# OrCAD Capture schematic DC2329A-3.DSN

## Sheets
1 PAGE1: size Custom; title: 17V, 3.5A DUAL SYNCHRONOUS STEP-DOWN; rev: 3; company: TM; note: REGULATOR WITH ULTRA-LOW QUIESCENT CURRENT
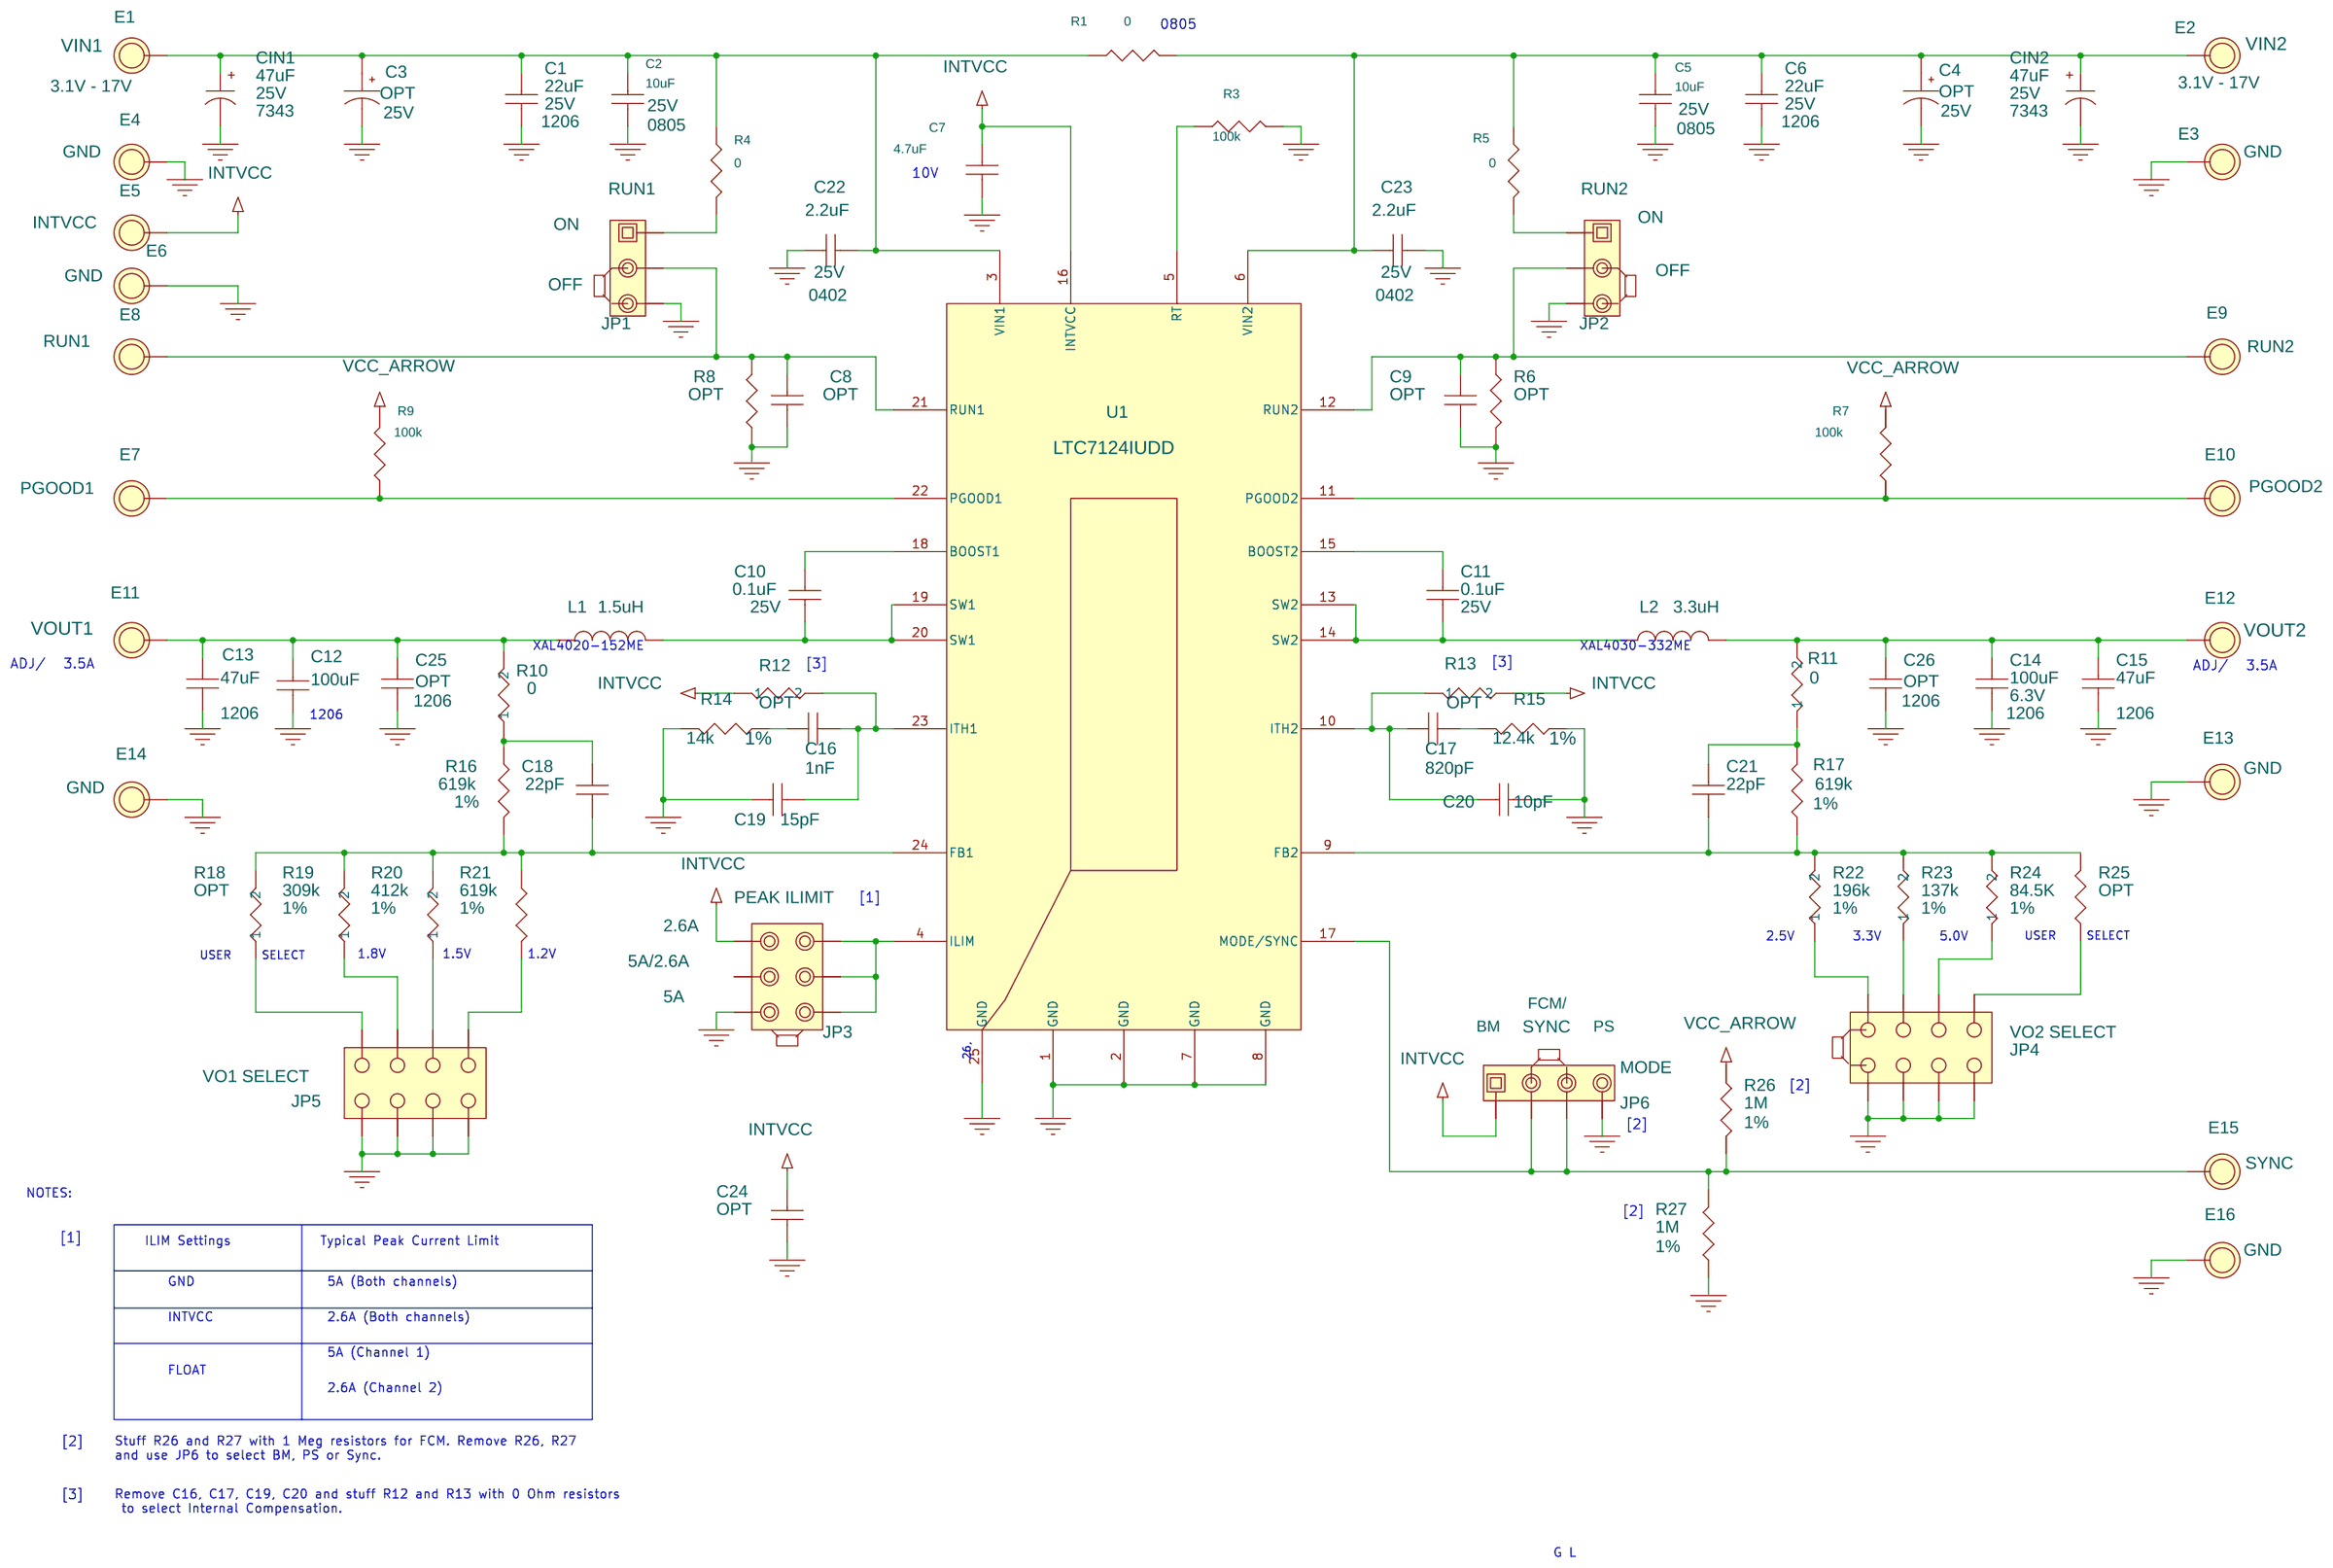
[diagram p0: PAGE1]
2 PAGE2: size A
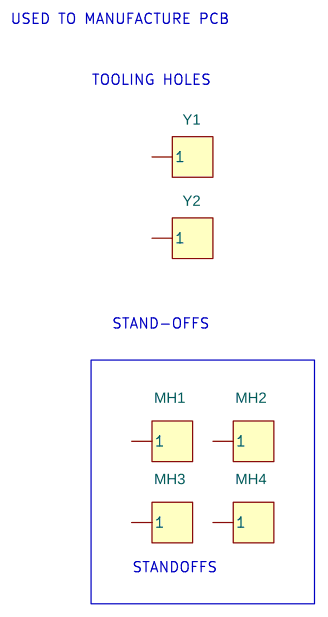
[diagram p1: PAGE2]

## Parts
sheet PAGE1
C1  22uF  [1206]
C2  10uF  [0805]
C3  OPT  [CAP\SANYO\SVPA_E7]
C4  OPT  [CAP\SANYO\SVPA_E7]
C5  10uF  [0805]
C6  22uF  [1206]
C7  4.7uF  [0603]
C8  OPT  [0603]
C9  OPT  [0603]
C10  0.1uF  [0603]
C11  0.1uF  [0603]
C12  100uF  [1206]
C13  47uF  [1206]
C14  100uF  [1206]
C15  47uF  [1206]
C16  1nF  [0603]
C17  820pF  [0603]
C18  22pF  [0603]
C19  15pF  [0603]
C20  10pF  [0603]
C21  22pF  [0603]
C22  2.2uF  [0402]
C23  2.2uF  [0402]
C24  OPT  [0603]
C25  OPT  [1206]
C26  OPT  [1206]
CIN1  47uF  [7343]
CIN2  47uF  [7343]
E1  3.1V - 17V  [TP\MMX\2501-2]
E2  3.1V - 17V  [TP\MMX\2501-2]
E3  2.7V - 17V  [TP\MMX\2501-2]
E4  2.7V - 17V  [TP\MMX\2501-2]
E5  3.6V  [TP\MMX\2501-2]
E6  2.7V - 17V  [TP\MMX\2501-2]
E7  3A  [TP\MMX\2501-2]
E8  2.7V - 17V  [TP\MMX\2501-2]
E9  2.7V - 17V  [TP\MMX\2501-2]
E10  3A  [TP\MMX\2501-2]
E11  ADJ  [TP\MMX\2501-2]
E12  ADJ  [TP\MMX\2501-2]
E13  2.7V - 17V  [TP\MMX\2501-2]
E14  2.7V - 17V  [TP\MMX\2501-2]
E15  3A  [TP\MMX\2501-2]
E16  2.7V - 17V  [TP\MMX\2501-2]
JP1  3 Pins 2mm Ctrs.  [SIP\3P\2MM]
JP2  3 Pins 2mm Ctrs.  [SIP\3P\2MM]
JP3  2 Pins 2mm Ctrs.  [HDR\3X2\2MM]
JP4  VO2 SELECT  [HDR2X4_2MM]
JP5  VO1 SELECT  [HDR2X4_2MM]
JP6  3 Pins 2mm Ctrs.  [HDR_1X4_2MM]
L1  1.5uH  [IND\CLCRFT\XAL4020]
L2  3.3uH  [IND\CLCRFT\XAL4030]
R1  0  [0805]
R3  100k  [0603]
R4  0  [0603]
R5  0  [0603]
R6  OPT  [0603]
R7  100k  [0603]
R8  OPT  [0603]
R9  100k  [0603]
R10  0  [0603]
R11  0  [0603]
R12  OPT  [0603]
R13  OPT  [0603]
R14  14k  [0603]
R15  12.4k  [0603]
R16  619k  [0603]
R17  619k  [0603]
R18  OPT  [0603]
R19  309k  [0603]
R20  412k  [0603]
R21  619k  [0603]
R22  196k  [0603]
R23  137k  [0603]
R24  84.5K  [0603]
R25  OPT  [0603]
R26  1M  [0603]
R27  1M  [0603]
U1  LTC7124IUDD  [LT_UDD24_3X5]
XJP1  2mm Ctrs.
XJP2  2mm Ctrs.
XJP3  2mm Ctrs.
XJP4  2mm Ctrs.
XJP5  2mm Ctrs.
XJP6  2mm Ctrs.
sheet PAGE2
MH1  CON1  [KEYSTONE_8831]
MH2  CON1  [KEYSTONE_8831]
MH3  CON1  [KEYSTONE_8831]
MH4  CON1  [KEYSTONE_8831]
Y1  CON1  [TOOL\ALGNHL\70]
Y2  CON1  [TOOL\ALGNHL\70]

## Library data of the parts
C1 C6 = CAP_NP: CAP, 1206 22uF10% 25V X5R; Part Number: AVX 12063D226KAT2A; Tolerance: X5R; Voltage: 25V
C2 C5 = CAP: CAP, 0805 10uF 10% 25V ,X5R; CLASS: DISCRETE; Dielectric Type: X5R; FPLIST: CC0805N,CC0805L,CC0805M; Manufacturer: MURATA; Manufacturer PN: GRM219R61E106KA12D; PART_NUMBER: 150-3455; Part Number: MURATA GRM219R61E106KA12D; Rated Voltage: 25V; Tolerance: 10%; UserField01: Thickness = 0.85 +/-0.1mm
C3 C4 = CAP_POL: CAP, 100uF 20% 25V ELEC OPTION; Part Number: PANASONIC 25SVPF100M OPTION; VOLTAGE: 25V
C7 = CAP_NP: CAP, 0603 4.7uF 10% 10V X5R; Part Number: AVX 0603ZD475KAT2A
C8 C9 C24 = CAP_NP: CAP, 0603 OPTION; Part Number: OPTION
C10 C11 = CAP_NP_0: CAP, 0603 0.1uF 10% 50V X7R; 1ST PART FIELD: 25V; Part Number: TDK C1608X7R1H104K or AVX 06035C104KAT2A; Tol: OPT
C12 = CAP_NP: CAP, 1206 100uF 20% 6.3V X5R; Case: 10V; FIELD1: 0805; Part Number: MURATA GRM31CR60J107ME39L; Tolerance: X5R; Voltage: 6.3V
C13 C15 = CAP_NP: CAP, 1206 47uF 10% 10V X5R; Part Number: MURATA GRM31CR61A476KE15; Tolerance: X5R; Voltage: 10V
C14 = CAP_NP: CAP, 1206 100uF 20% 6.3V X5R; FIELD1: 0805; Part Number: MURATA GRM31CR60J107ME39L; Tolerance: X5R; Voltage: 6.3V
C16 = CAP_NP_0: CAP, 0603 1nF 5% 50V X7R; 1ST PART FIELD: 1%; Part Number: AVX 06035C102JAT2A; Tol: PT
C17 = CAP_NP_0: CAP, 0603 820pF 5% 50V C0G; 1ST PART FIELD: 1%; Part Number: AVX 06035A821JAT2A
C18 C21 = CAP_NP: CAP, 0603 22pF 5% 50V C0G; Case: 1206; Part Number: MURATA GRM1885C1H220JA01D; Tolerance: NPO; Voltage: 50V
C19 = CAP: CAP, 0603 15pF 5% 50V C0G; CLASS: DISCRETE; Dielectric Type: C0G; FPLIST: CC0603N,CC0603L,CC0603M; Manufacturer: AVX; Manufacturer PN: 06035A150JAT2A; PART_NUMBER: TMP-2478; Part Number: AVX 06035A150JAT2A; Rated Voltage: 50V; Tolerance: 5%
C20 = CAP_NP_0: CAP, 0603 10pF 5% 50V C0G; 1ST PART FIELD: 1210; Part Number: AVX 06035A100JAT2A
C22 C23 = CAP_NP: CAP, 0402 2.2uF 10% 25V X5R; 1st Part Field: 25V; Part Number: MURATA GRM155R61E225KE11D
C25 C26 = CAP_NP: CAP, 1206 OPTION; Part Number: OPTION; Tolerance: X5R; Voltage: 10V
CIN1 CIN2 = CAP+7343: CAP, 47uF 20% 25V 50m Ohm; 1ST PART FIELD: 25V; 2ND PART FIELD: OPT; 4TH PART FIELD: [1]; Part Number: AVX TCJE476M025R0050
E1 = E_4: TURRET; INPUT: VIN1; Part Number: MILL-MAX 2501-2-00-80-00-00-07-0; STATUS: 1.6V, 1.8V, 2.0V OR 2.5V @ 15A
E2 = E_4: TURRET; INPUT: VIN2; Part Number: MILL-MAX 2501-2-00-80-00-00-07-0; STATUS: 1.6V, 1.8V, 2.0V OR 2.5V @ 15A
E3 E4 E6 E13 E14 E16 = E_4: TURRET; INPUT: GND; Part Number: MILL-MAX 2501-2-00-80-00-00-07-0; STATUS: 1.6V, 1.8V, 2.0V OR 2.5V @ 15A
E5 = E_4: TURRET; INPUT: INTVCC; Part Number: MILL-MAX 2501-2-00-80-00-00-07-0; STATUS: 1.6V, 1.8V, 2.0V OR 2.5V @ 15A
E7 = E_4: TURRET; INPUT: PGOOD1; Part Number: MILL-MAX 2501-2-00-80-00-00-07-0; STATUS: 1.6V, 1.8V, 2.0V OR 2.5V @ 15A
E8 = E_4: TURRET; INPUT: RUN1; Part Number: MILL-MAX 2501-2-00-80-00-00-07-0; STATUS: 1.6V, 1.8V, 2.0V OR 2.5V @ 15A
E9 = E_4: TURRET; INPUT: RUN2; Part Number: MILL-MAX 2501-2-00-80-00-00-07-0; STATUS: 1.6V, 1.8V, 2.0V OR 2.5V @ 15A
E10 = E_4: TURRET; INPUT: PGOOD2; Part Number: MILL-MAX 2501-2-00-80-00-00-07-0; STATUS: 1.6V, 1.8V, 2.0V OR 2.5V @ 15A
E11 = E_4: TURRET; INPUT: VOUT1; Part Number: MILL-MAX 2501-2-00-80-00-00-07-0; STATUS: 1.6V, 1.8V, 2.0V OR 2.5V @ 15A
E12 = E_4: TURRET; INPUT: VOUT2; Part Number: MILL-MAX 2501-2-00-80-00-00-07-0; STATUS: 1.6V, 1.8V, 2.0V OR 2.5V @ 15A
E15 = E_4: TURRET; INPUT: SYNC; Part Number: MILL-MAX 2501-2-00-80-00-00-07-0; STATUS: 1.6V, 1.8V, 2.0V OR 2.5V @ 15A
JP1 = Samtec_TMM-103-02-L-S: HEADER, 3PIN, 2mm; 11th Part Field: OFF; 12th Part Field: RUN1; 9th Part Field: ON; Part Number: SAMTEC TMM-103-02-L-S
JP2 = Samtec_TMM-103-02-L-S: HEADER, 3PIN, 2mm; 11th Part Field: OFF; 12th Part Field: RUN2; 9th Part Field: ON; Part Number: SAMTEC TMM-103-02-L-S
JP3 = Samtec_TMM-: HEADER, 3PIN, DBL ROW 2mm; 4th Part Field: 2.6A; 5th Part Field: 5A; 7th Part Field: 5A/2.6A; 9th Part Field: PEAK ILIMIT; Part Number: SULLINS NRPN032PAEN-RC
JP4 JP5 = hdr2X4_2MM: HEADER, 4PIN, DBL R0W 2mm; Part Number: SAMTEC TMM-104-02-L-D
JP6 = Samtec_TMM-103-02-L-S_0: HEADER, 4PIN, 2mm; 11th Part Field: FCM/; 12th Part Field: MODE; 4th Part Field: PS; 5th Part Field: SYNC; 9th Part Field: BM; Part Number: SAMTEC TMM-104-02-L-S
L1 = INDUCTOR: IND, 1.5uH; Part Number: COILCRAFT XAL4020-152ME
L2 = INDUCTOR: IND, 3.3uH; Part Number: COILCRAFT XAL4030-332ME
R1 = RESISTOR: RES, 0805 0 OHM JUMPER; Part Number: VISHAY CRCW08050000Z0EA
R3 R7 R9 = RESISTOR: RES, 0603 100K OHM 1% 0.1W; 1st Part Field: 1%; Part Number: VISHAY CRCW0603100KFKEA
R4 R5 = RESISTOR: RES, 0603 0 OHM JUMPER; 1st Part Field: 1%; Part Number: VISHAY CRCW06030000Z0EA
R6 R8 = RESISTOR: RES, 0603 OPTION; Part Number: OPTION
R10 = R_3: RES, 0603 0 OHM JUMPER; 5%: 1%; Part Number: VISHAY CRCW06030000Z0EA
R11 = R_9: RES, 0603 0 OHM JUMPER; 5%: 1%; Part Number: VISHAY CRCW06030000Z0EA
R12 = R_1: RES, 0603 0 OHM JUMPER OPTION; 5%: 1%; Part Number: VISHAY CRCW06030000Z0EA OPTION
R13 = R_6: RES, 0603 0 OHM JUMPER OPTION; 5%: 1%; Part Number: VISHAY CRCW06030000Z0EA OPTION
R14 = RESISTOR: RES, 0603 14K OHMS 1% 0.1W; Part Number: VISHAY CRCW060314K0FKEA; Tol: 1%
R15 = RESISTOR: RES, 0603 12.4K OHMS 1% 0.1W; Part Number: VISHAY CRCW060312K4FKEA; Tol: 1%
R16 R17 R21 = RESISTOR: RES, 0603 619K OHM 1% 1/10W; Part Number: VISHAY CRCW0603619KFKEA; Tol: 1%
R18 = R_7: RES, 0603 OPTION; 5%: 1%; Part Number: OPTION; Tol: 1%
R19 = R: RES, 0603 309K OHMS 1% 1/10W; 5%: 1%; Part Number: VISHAY CRCW0603309KFKEA; Tol: 1%
R20 = R_4: RES, 0603 412K OHM 1% 1/10W; 5%: 1%; Part Number: VISHAY CRCW0603412KFKEA; Tol: 1%
R22 = R_5: RES, 0603 196K OHM 1% 1/10W; 5%: 1%; Part Number: VISHAY CRCW0603196KFKEA; Tol: 1%
R23 = R_2: RES, 0603 137K OHM 1% 1/10W; 5%: 1%; Part Number: VISHAY CRCW0603137KFKEA; Tol: 1%
R24 = R_8: RES, 0603 84.5K OHM 1% 1/10W; 5%: 1%; Part Number: VISHAY CRCW060384K5FKEA
R25 = RESISTOR: RES, 0603 OPTION; Part Number: OPTION; Tolerance: 1%
R26 R27 = RESISTOR: RES, 0603 1M OHMS 1% 1/10W; Part Number: VISHAY CRCW06031M00FKEA; Tol: 1%
U1 = LTC7124EUDD_2: IC, DUAL DC/DC SYNCHRONOUS STEP-DOWN REGULATOR; Part Number: LINEAR TECH LTC7124IUDD
XJP1-XJP4 XJP6 = Samtec_2SN-BK-G: SHUNT, 2mm; Part Number: SAMTEC 2SN-BK-G
XJP5 = Samtec_2SN-BK-G_0: SHUNT, 2mm; Part Number: SAMTEC 2SN-BK-G
MH1-MH4 = CON1: STANDOFF, SNAP ON; Part Number: KEYSTONE_8834
Y1 Y2 = CON1: DO NOT STUFF; Part Number: PADS ONLY

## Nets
GND: C1.2 C2.2 C3.2 C4.2 C5.2 C6.2 C7.2 C8.2 C9.2 C12.2 C13.2 C14.2 C15.2 C19.1 C20.2 C22.1 C23.2 C24.2 C25.2 C26.2 CIN1.2 CIN2.2 E3.1(A) E4.1(A) E6.1(A) E13.1(A) E14.1(A) E16.1(A) JP1.3 JP2.3 JP3.5 JP4.1 JP4.3 JP4.5 JP4.7 JP5.1 JP5.3 JP5.5 JP5.7 JP6.4 R3.2 R6.2 R8.2 R14.2 R15.1 R27.1 U1.1(GND) U1.2(GND) U1.7(GND) U1.8(GND) U1.25(GND)
INTVCC: C7.1 C24.1 E5.1(A) JP3.1 JP6.1 R7.2 R9.2 R12.1 R13.2 R26.2 U1.16(INTVCC)
N16791784: C1.1 C2.1 C3.1 C22.2 CIN1.1 E1.1(A) R1.1 R4.2 U1.3(VIN1)
N16804265: C21.2 R17.1 R22.2 R23.2 R24.2 R25.2 U1.9(FB2)
N16854814: C21.1 R11.1 R17.2
N16889679: C4.1 C5.1 C6.1 C23.1 CIN2.1 E2.1(A) R1.2 R5.1 U1.6(VIN2)
N16949815: C8.1 E8.1(A) JP1.2 R8.1 U1.21(RUN1)
N16951518: C9.1 E9.1(A) JP2.2 R6.1 U1.12(RUN2)
N16954109: E7.1(A) R9.1 U1.22(PGOOD1)
N16955230: E10.1(A) R7.1 U1.11(PGOOD2)
N16964143: C11.1 U1.15(BOOST2)
N16964313: C11.2 L2.2 U1.13(SW2) U1.14(SW2)
N16970289: C14.1 C15.1 C26.1 E12.1(A) L2.1 R11.2
N16987719: C17.2 R15.2
N16991259: C17.1 C20.1 R13.1 U1.10(ITH2)
N17005440: C10.2 L1.2 U1.19(SW1) U1.20(SW1)
N17006016: C10.1 U1.18(BOOST1)
N17008245: C12.1 C13.1 C25.1 E11.1(A) L1.1 R10.2
N17016060: C16.2 C19.2 R12.2 U1.23(ITH1)
N17060465: E15.1(A) JP6.2 JP6.3 R26.1 R27.2 U1.17(MODE/SYNC)
N17070454: C18.1 R10.1 R16.2
N17074942: C18.2 R16.1 R18.2 R19.2 R20.2 R21.2 U1.24(FB1)
N17129305: JP3.2 JP3.4 JP3.6 U1.4(ILIM)
N17289228: R3.1 U1.5(RT)
N17307870: C16.1 R14.1
N17403248: JP1.1 R4.1
N17487458: JP4.6 R23.1
N17487708: JP4.8 R22.1
N17488467: JP4.4 R24.1
N17489238: JP4.2 R25.1
N17536250: JP2.1 R5.2
N17605054: JP5.8 R18.1
N17605833: JP5.6 R19.1
N17608579: JP5.4 R20.1
N17608853: JP5.2 R21.1

Not connected (* = marked no-connect by the designer): JP3 3; MH1 1; MH2 1; MH3 1; MH4 1; Y1 1; Y2 1

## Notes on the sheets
sheet 1
- 0805
- 10V
- ADJ/
- 3.5A
- XAL4020-152ME
- [3]
- [3]
- XAL4030-332ME
- ADJ/
- 3.5A
- 1206
- [1]
- USER
- SELECT
- 1.8V
- 1.5V
- 1.2V
- 2.5V
- 3.3V
- 5.0V
- USER
- SELECT
- 26,
- [2]
- [2]
- NOTES:
- [2]
- [1]
- ILIM Settings
- Typical Peak Current Limit
- GND
- 5A (Both channels)
- INTVCC
- 2.6A (Both channels)
- 5A (Channel 1)
- FLOAT
- 2.6A (Channel 2)
- [2]
- Stuff R26 and R27 with 1 Meg resistors for FCM. Remove R26, R27
  and use JP6 to select BM, PS or Sync.
- [3]
- Remove C16, C17, C19, C20 and stuff R12 and R13 with 0 Ohm resistors
   to select Internal Compensation.
- G L
sheet 2
- USED TO MANUFACTURE PCB
- TOOLING HOLES
- STAND-OFFS
- STANDOFFS
